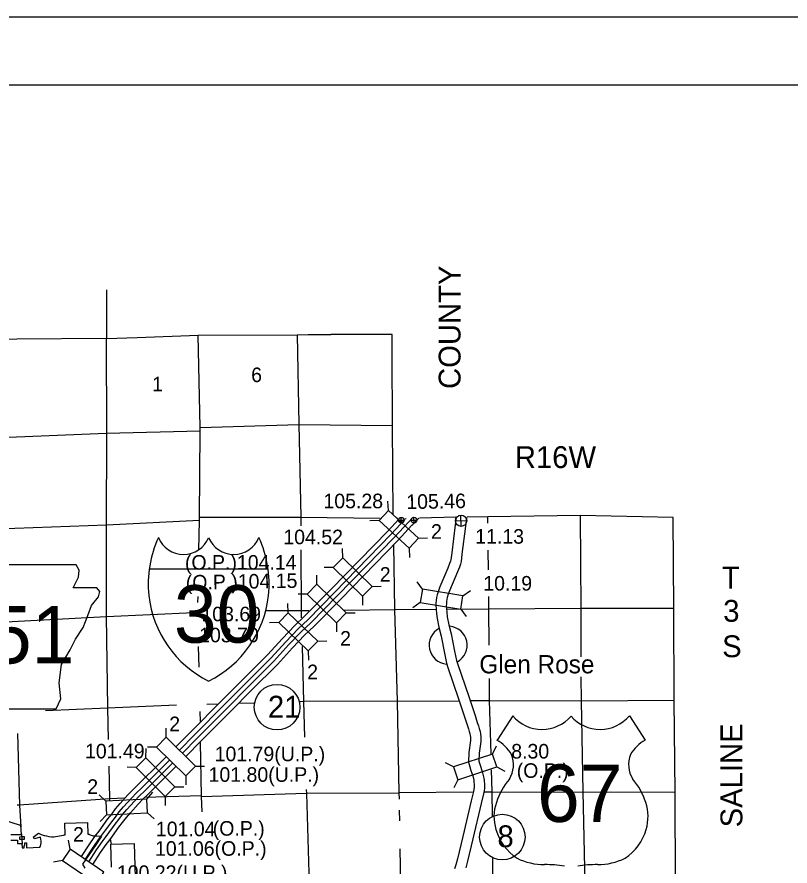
# Model space of a CAD drawing. Extents: x 369523 to 838377, y 495025 to 936819.
# Drawn here: x 659736 to 704526, y 887609 to 936819 of the extents above; entities that cross this region are included whole.
import ezdxf

# ---------------------------------------------------------------- set-up
doc = ezdxf.new("R2010")
doc.units = 0
for name, color, linetype in [('1', 7, 'Continuous'), ('2', 7, 'Continuous'), ('21', 7, 'Continuous'), ('22', 7, 'Continuous'), ('6', 7, 'Continuous'), ('DSN_BRDG_Annotation', 7, 'Continuous'), ('DSN_DRFT_Common-Annotations', 7, 'Continuous'), ('DSN_DRFT_Common-Line', 7, 'Continuous'), ('DSN_DRFT_Junk-No-Plot', 7, 'Continuous'), ('Level 11', 7, 'Continuous'), ('Level 15', 7, 'Continuous'), ('Level 2', 7, 'Continuous'), ('Level 21', 7, 'Continuous'), ('Level 22', 7, 'Continuous'), ('Level 23', 7, 'Continuous'), ('Level 6', 7, 'Continuous')]:
    doc.layers.add(name, color=color, linetype=linetype)

msp = doc.modelspace()

# ---------------------------------------------------------------- linework, layer by layer
at = {"layer": '1'}
for start, end in [(118.4516, 265.0982), (298.9747, 85.3232)]:
    msp.add_arc((684719, 900411), 1100, start, end, dxfattribs=at)
at = {"layer": '2'}
msp.add_line((667400, 904842), (674283, 904842), dxfattribs=at)
for centre, radius, start, end in [((673796, 903945), 6458, 155.2204, 185.7928), ((669390, 907245), 1573, 202.1459, 337.3414), ((672293, 907245), 1573, 202.6586, 337.8541), ((667887, 903945), 6458, 354.2072, 24.7796), ((673677, 904000), 6346, 186.3923, 243.4571), ((668006, 904000), 6346, 296.5429, 353.6077)]:
    msp.add_arc(centre, radius, start, end, dxfattribs=at)
at = {"layer": '21'}
for p, q in [((454599, 936819), (750279, 936819)), ((744999, 932859), (470439, 932859)), ((700901, 902313), (700901, 902313))]:
    msp.add_line(p, q, dxfattribs=at)
at = {"layer": '22'}
msp.add_lwpolyline([(655173, 905068), (655572, 902403), (655395, 898362), (655750, 898140), (656416, 898140), (656416, 896719), (662012, 896719), (662278, 897296), (662189, 898229), (662323, 899295), (662811, 900138), (663122, 900760), (663566, 901426), (663832, 902137), (664055, 902714), (664454, 903203), (664543, 903513), (664365, 903735), (662989, 903735), (663300, 904357), (663344, 904757), (663160, 905064)], close=True, dxfattribs=at)
at = {"layer": '6'}
for p, q in [((688460, 896309), (687552, 894904)), ((695217, 896309), (696125, 894904))]:
    msp.add_line(p, q, dxfattribs=at)
for centre, radius, start, end in [((690153, 897733), 2211, 220.075, 319.6701), ((693524, 897733), 2211, 220.3299, 319.925), ((686364, 892864), 2361, 30.7809, 59.9883), ((697313, 892864), 2361, 120.0117, 149.2191), ((686884, 893487), 1618, 328.8105, 21.2108), ((696793, 893487), 1618, 158.7892, 211.1895), ((691116, 890169), 3776, 138.9565, 162.6913), ((692561, 890169), 3776, 17.3087, 41.0435), ((689869, 890479), 2495, 160.9576, 197.3819), ((693807, 890479), 2495, 342.6181, 19.0424), ((690276, 890486), 2887, 195.1074, 237.1312), ((693401, 890486), 2887, 302.8688, 344.8926), ((690329, 891395), 3707, 244.0771, 269.5779), ((693348, 891395), 3707, 270.4221, 295.9229), ((690415, 880899), 6790, 81.1942, 90.9539), ((693262, 880899), 6790, 89.0461, 98.8058)]:
    msp.add_arc(centre, radius, start, end, dxfattribs=at)
at = {"layer": 'DSN_DRFT_Common-Annotations'}
for p, q in [((685477, 907294), (685462, 907945)), ((681840, 907647), (682165, 907655)), ((682006, 907488), (681999, 907814)), ((682573, 907653), (682899, 907661)), ((682740, 907494), (682732, 907820)), ((685144, 907612), (685795, 907627))]:
    msp.add_line(p, q, dxfattribs=at)
for centre, radius in [((685469, 907619), 326), ((682003, 907651), 163), ((682736, 907657), 163)]:
    msp.add_circle(centre, radius, dxfattribs=at)
at = {"layer": 'DSN_DRFT_Common-Line'}
for centre in [(674804, 896819), (687857, 889288)]:
    msp.add_circle(centre, 1320, dxfattribs=at)
at = {"layer": 'Level 11'}
for points in [[(685177, 907818), (685122, 907379)], [(685782, 907816), (685717, 907303)], [(685121, 907377), (684924, 905760), (684872, 905362), (684850, 905269), (684804, 905135), (684703, 904881), (684240, 903783), (684158, 903550), (684090, 903336), (684051, 903172), (684022, 902999), (684013, 902835), (684009, 902679), (684014, 902553), (684015, 902477), (684040, 902254), (684073, 901953), (684181, 901452), (684307, 900930), (684497, 899941), (684628, 899374), (684695, 899116), (685323, 897304), (685709, 896137), (685838, 895740), (685901, 895556), (685944, 895411), (685980, 895271), (685995, 895193), (686010, 895057), (686005, 894879), (685910, 894187), (685900, 893620), (685967, 893353), (686038, 893139), (686140, 892843), (686205, 892590), (686215, 892517), (686223, 892323), (686224, 892157), (686214, 892061), (686188, 891923), (686055, 891381), (685568, 889323), (685255, 888033), (685160, 887681), (685088, 887455)], [(685717, 907305), (685520, 905684), (685463, 905255), (685428, 905103), (685366, 904926), (685258, 904653), (684800, 903567), (684727, 903360), (684668, 903176), (684639, 903054), (684620, 902934), (684613, 902809), (684609, 902684), (684614, 902570), (684615, 902514), (684636, 902320), (684666, 902049), (684766, 901586), (684893, 901057), (685084, 900065), (685211, 899517), (685270, 899290), (685891, 897497), (686279, 896324), (686407, 895930), (686473, 895738), (686522, 895571), (686566, 895404), (686589, 895282), (686611, 895082), (686604, 894830), (686510, 894141), (686501, 893689), (686544, 893520), (686606, 893331), (686715, 893016), (686794, 892709), (686814, 892573), (686823, 892335), (686824, 892128), (686809, 891975), (686775, 891796), (686638, 891240), (686152, 889184), (685836, 887884), (685736, 887512)]]:
    msp.add_lwpolyline(points, dxfattribs=at)
at = {"layer": 'Level 15'}
for points in [[(670273, 905919), (670304, 907639), (670308, 907804), (670351, 912810), (670354, 913016), (670233, 918373)], [(670218, 902884), (670224, 903226)], [(670292, 899128), (670262, 900334)], [(670362, 895994), (670354, 896562)], [(670460, 890744), (670422, 891633), (670421, 891685), (670378, 894775)]]:
    msp.add_lwpolyline(points, dxfattribs=at)
at = {"layer": 'Level 2'}
for points in [[(658574, 890400), (659859, 889988), (659934, 889991), (659979, 889423), (659384, 889416)], [(659387, 889107), (659762, 889114), (659766, 888905), (660020, 888910), (660041, 888654), (660159, 888659), (660160, 888795), (660179, 888794), (660183, 888795), (660187, 888797), (660191, 888806), (660191, 888818), (660191, 888832), (660191, 888952), (660285, 888952), (660284, 888664), (661066, 888697), (661091, 888761), (661120, 888857), (661130, 888945), (661136, 889007), (661132, 889075), (661124, 889150), (661096, 889276), (660729, 889192), (660709, 889244), (660682, 889290), (660980, 889520), (661060, 889476), (661133, 889435), (661191, 889408), (661308, 889387), (661358, 889378), (661451, 889359), (661585, 889328), (661745, 889296), (661811, 889299), (661878, 889304), (661973, 889313), (662107, 889336), (662206, 889352), (662317, 889371), (662440, 889401), (662497, 889415), (662534, 889418), (662512, 890087), (663826, 890136), (663847, 889454), (663890, 889450), (663915, 889447), (663972, 889421), (664026, 889398), (664090, 889378), (664159, 889366), (664354, 889352), (664637, 889332), (664307, 888832), (663536, 887724), (663666, 887491)], [(665211, 887547), (665176, 888868), (666524, 888911), (666599, 886299)]]:
    msp.add_lwpolyline(points, dxfattribs=at)
msp.add_lwpolyline([(660152, 889148), (659907, 889143), (659898, 889308), (659988, 889312), (660143, 889319)], close=True, dxfattribs=at)
at = {"layer": 'Level 21'}
for p, q in [((681252, 908219), (681231, 908747)), ((680716, 907637), (680188, 907615)), ((683000, 906609), (683527, 906631)), ((678609, 905476), (678603, 906004)), ((682463, 906027), (682485, 905499)), ((678056, 904909), (677528, 904903)), ((677106, 903938), (677101, 904466)), ((683231, 903660), (682923, 904089)), ((680309, 903816), (680837, 903822)), ((685576, 903275), (686004, 903583)), ((676552, 903373), (676024, 903368)), ((679756, 903249), (679762, 902721)), ((675447, 902288), (675436, 902816)), ((683103, 902878), (682674, 902570)), ((678802, 902274), (679330, 902279)), ((685447, 902493), (685755, 902065)), ((674899, 901716), (674371, 901705)), ((678247, 901709), (678252, 901181)), ((677162, 900643), (677690, 900654)), ((676613, 900072), (676625, 899544)), ((668386, 895068), (668383, 895596)), ((667209, 893885), (667212, 894413)), ((667829, 894504), (667301, 894501)), ((687287, 894101), (687525, 894572)), ((666646, 893328), (666118, 893331)), ((670076, 893397), (670604, 893400)), ((685031, 893357), (684559, 893594)), ((687535, 893349), (688007, 893111)), ((669519, 892834), (669522, 892306)), ((668879, 892195), (669407, 892192)), ((685279, 892605), (685041, 892133)), ((664880, 891376), (664489, 891730)), ((667253, 891492), (667608, 891883)), ((668316, 891638), (668313, 891110)), ((667292, 890701), (667683, 890346)), ((664919, 890585), (664564, 890193)), ((662812, 888580), (662713, 889099)), ((662366, 887925), (661848, 887826))]:
    msp.add_line(p, q, dxfattribs=at)
for points in [[(683000, 906609), (681252, 908219), (680716, 907637), (682463, 906027)], [(680309, 903816), (678609, 905476), (678056, 904909), (679756, 903249)], [(676552, 903373), (678247, 901709), (678802, 902274), (677106, 903938)], [(683103, 902878), (685447, 902493), (685576, 903275), (683231, 903660)], [(677162, 900643), (675447, 902288), (674899, 901716), (676613, 900072)], [(670076, 893397), (668386, 895068), (667829, 894504), (669519, 892834)], [(666646, 893328), (668316, 891638), (668879, 892195), (667209, 893885)], [(687287, 894101), (685031, 893357), (685279, 892605), (687535, 893349)], [(664919, 890585), (667292, 890701), (667253, 891492), (664880, 891376)], [(662366, 887925), (664331, 886589), (664776, 887244), (662812, 888580)]]:
    msp.add_lwpolyline(points, close=True, dxfattribs=at)
at = {"layer": 'Level 22'}
for points in [[(675967, 918404), (676058, 913211), (676189, 907821), (676189, 907319)], [(665041, 894945), (664998, 896787), (664917, 902085), (664929, 907361), (664938, 912677), (664932, 918184)], [(670354, 913016), (676066, 913191), (681497, 913133)], [(670351, 912810), (664932, 912677), (659710, 912471), (654381, 912279), (649169, 912279), (643845, 912269)], [(692370, 907929), (692406, 902523), (692412, 899726)], [(670304, 907639), (664925, 907367), (659610, 907181), (654331, 907002), (649137, 906828), (643693, 907052)], [(680783, 907759), (676183, 907814), (670308, 907804)], [(687016, 907489), (687012, 907856)], [(681895, 891477), (681889, 891850), (681790, 897156), (681636, 902469), (681569, 906222)], [(676191, 905939), (676194, 902415), (676206, 901990)], [(687050, 904778), (687036, 905922)], [(687096, 900417), (687079, 902511), (687070, 903228)], [(697800, 902537), (692392, 902537), (687085, 902505), (684668, 902482)], [(654322, 901515), (664916, 902071), (669986, 902305)], [(676655, 902407), (676212, 902403), (674142, 902401)], [(681644, 902453), (678688, 902426)], [(684005, 902476), (681644, 902453)], [(676252, 900339), (676340, 897143), (676404, 895082)], [(692414, 898567), (692417, 897174), (692524, 891900), (692638, 886605)], [(687209, 894103), (687123, 897198), (687113, 898471)], [(681790, 897156), (676338, 897141), (676096, 897133)], [(685334, 897171), (681760, 897147)], [(697811, 897211), (692419, 897168), (687126, 897182), (686038, 897175)], [(668973, 896934), (664983, 896754), (661381, 896613)], [(671340, 896983), (670741, 896964)], [(673498, 897051), (672582, 897022)], [(659765, 895286), (659872, 891142), (659968, 889871)], [(665124, 891417), (665123, 891486), (665078, 893393)], [(687282, 890491), (687270, 891905), (687235, 893176)], [(670421, 891685), (667131, 891578)], [(670422, 891633), (676489, 891827), (681897, 891842)], [(676498, 892050), (676505, 891819), (676659, 886561)], [(686137, 891881), (681897, 891842)], [(697867, 891894), (692524, 891876), (687268, 891891), (686802, 891887)], [(665971, 891540), (665112, 891512), (659856, 891144), (659744, 891143)], [(681918, 890220), (681907, 890848)], [(665145, 890553), (665145, 890567)], [(659999, 889467), (660044, 888873)], [(665185, 888922), (665180, 889126)], [(681983, 886544), (681947, 888607)], [(687315, 886556), (687302, 888039)]]:
    msp.add_lwpolyline(points, dxfattribs=at)
at = {"layer": 'Level 23'}
for points in [[(681883, 907741), (681222, 907023), (677939, 903662)], [(682236, 907718), (681422, 906834), (678136, 903470)], [(682420, 907548), (681603, 906662), (678315, 903295)], [(682261, 907744), (682238, 907720)], [(682638, 907773), (682417, 907546)], [(683024, 907776), (682615, 907354)], [(682622, 907362), (681803, 906473), (678511, 903103)], [(668941, 894508), (669848, 895426), (671553, 897148), (672764, 898368), (674245, 899850), (675111, 900800), (675831, 901550), (676388, 902081), (677940, 903662)], [(669135, 894313), (670044, 895232), (671748, 896954), (672958, 898174), (674443, 899660), (675312, 900612), (676025, 901355), (676581, 901885), (678136, 903470)], [(669315, 894139), (670221, 895056), (671926, 896778), (673136, 897998), (674624, 899487), (675495, 900441), (676201, 901178), (676756, 901707), (678314, 903295)], [(669515, 893951), (670417, 894863), (672121, 896585), (673330, 897804), (674823, 899297), (675696, 900253), (676396, 900983), (676949, 901511), (678511, 903102)], [(663474, 888158), (663914, 888829), (664248, 889325), (664488, 889631), (665009, 890345), (665225, 890617), (665447, 890914), (665709, 891226), (666165, 891729), (666459, 892051), (666757, 892330), (668093, 893650), (668365, 893925)], [(663707, 888013), (664143, 888677), (664470, 889163), (664708, 889466), (665228, 890179), (665443, 890449), (665662, 890743), (665916, 891045), (666368, 891543), (666655, 891857), (666948, 892131), (668287, 893455), (668559, 893731)], [(663904, 887857), (664351, 888539), (664673, 889016), (664907, 889315), (665427, 890027), (665641, 890297), (665858, 890588), (666104, 890880), (666553, 891375), (666833, 891681), (667121, 891951), (668464, 893279), (668730, 893548)], [(664131, 887701), (664580, 888387), (664895, 888854), (665126, 889149), (665646, 889861), (665859, 890129), (666074, 890417), (666311, 890699), (666756, 891190), (667029, 891488), (667312, 891753), (668658, 893084), (668940, 893369)]]:
    msp.add_lwpolyline(points, dxfattribs=at)
at = {"layer": 'Level 6'}
for points in [[(664922, 921003), (664932, 918184), (659725, 918140), (654446, 918124), (649176, 918116), (646792, 918127)], [(664932, 918184), (666700, 918251)], [(666700, 918251), (670233, 918373), (675967, 918404), (676611, 918409), (677924, 918413)], [(681478, 917312), (681470, 918423), (677924, 918413)], [(681540, 907972), (681497, 913133), (681478, 917312)], [(706663, 886551), (703182, 886595), (697893, 886574), (697867, 891894), (697811, 897211), (697800, 902537), (697751, 907812), (692370, 907929), (687012, 907856), (685816, 907832)], [(681812, 907755), (681750, 907754)], [(685157, 907820), (683062, 907779)]]:
    msp.add_lwpolyline(points, dxfattribs=at)

# ---------------------------------------------------------------- texts
at = {"layer": '1'}
msp.add_text('Glen Rose', height=1056, dxfattribs=at).set_placement((686522, 898776))
at = {"layer": '2'}
msp.add_text('30', height=3326.4, dxfattribs=at).set_placement((668826, 900555))
at = {"layer": '21'}
for s, p in [('COUNTY', (685436, 915259)), ('SALINE', (701765, 889851))]:
    msp.add_text(s, height=1267.2, rotation=90, dxfattribs=at).set_placement(p)
for s, height, p in [('R16W', 1267.2, (688581, 910675)), ('T', 1267, (700578, 903691)), ('3', 1267, (700656, 901766)), ('S', 1267, (700593, 899712))]:
    msp.add_text(s, height=height, dxfattribs=at).set_placement(p)
at = {"layer": '22'}
msp.add_text('51', height=3326.4, dxfattribs=at).set_placement((658110, 899352))
at = {"layer": '6'}
msp.add_text('67', height=3326.4, dxfattribs=at).set_placement((689867, 890165))
at = {"layer": 'DSN_BRDG_Annotation'}
msp.add_text('105.46', height=844.8, rotation=1, dxfattribs=at).set_placement((682299, 908295))
msp.add_text('11.13', height=844.8, dxfattribs=at).set_placement((686286, 906291))
at = {"layer": 'DSN_DRFT_Common-Line'}
for s, height, p in [('21', 1267.2, (674275, 896209)), ('8', 1267, (687575, 888699))]:
    msp.add_text(s, height=height, dxfattribs=at).set_placement(p)
at = {"layer": 'DSN_DRFT_Junk-No-Plot'}
for s, p in [('105.28', (677492, 908345)), ('104.52', (675168, 906259)), ('(O.P.)104.14', (669467, 904787)), ('10.19', (686753, 903573)), ('103.69', (670421, 901794)), ('103.70', (670289, 900575)), ('101.49', (663676, 893847)), ('8.30', (688372, 893839)), ('101.79(U.P.)', (671188, 893684)), ('101.80(U.P.)', (670837, 892489)), ('(O.P.)', (688692, 892719)), ('(O.P.)', (671078, 889369)), ('101.04', (667783, 889337)), ('101.06(O.P.)', (667731, 888204)), ('100.22(U.P.)', (665524, 886803))]:
    msp.add_text(s, height=844.8, dxfattribs=at).set_placement(p)
msp.add_text('(O.P.)104.15', height=844.8, rotation=1, dxfattribs=at).set_placement((669523, 903621))
at = {"layer": 'Level 21'}
for p in [(683723, 906576), (680757, 904089), (678457, 900381), (676551, 898438), (668558, 895423), (663807, 891790), (662984, 889019)]:
    msp.add_text('2', height=845, dxfattribs=at).set_placement(p)
at = {"layer": 'Level 22'}
for s, p in [('6', (673304, 915655)), ('1', (667565, 915121))]:
    msp.add_text(s, height=845, dxfattribs=at).set_placement(p)

doc.saveas('drawing.dxf')
